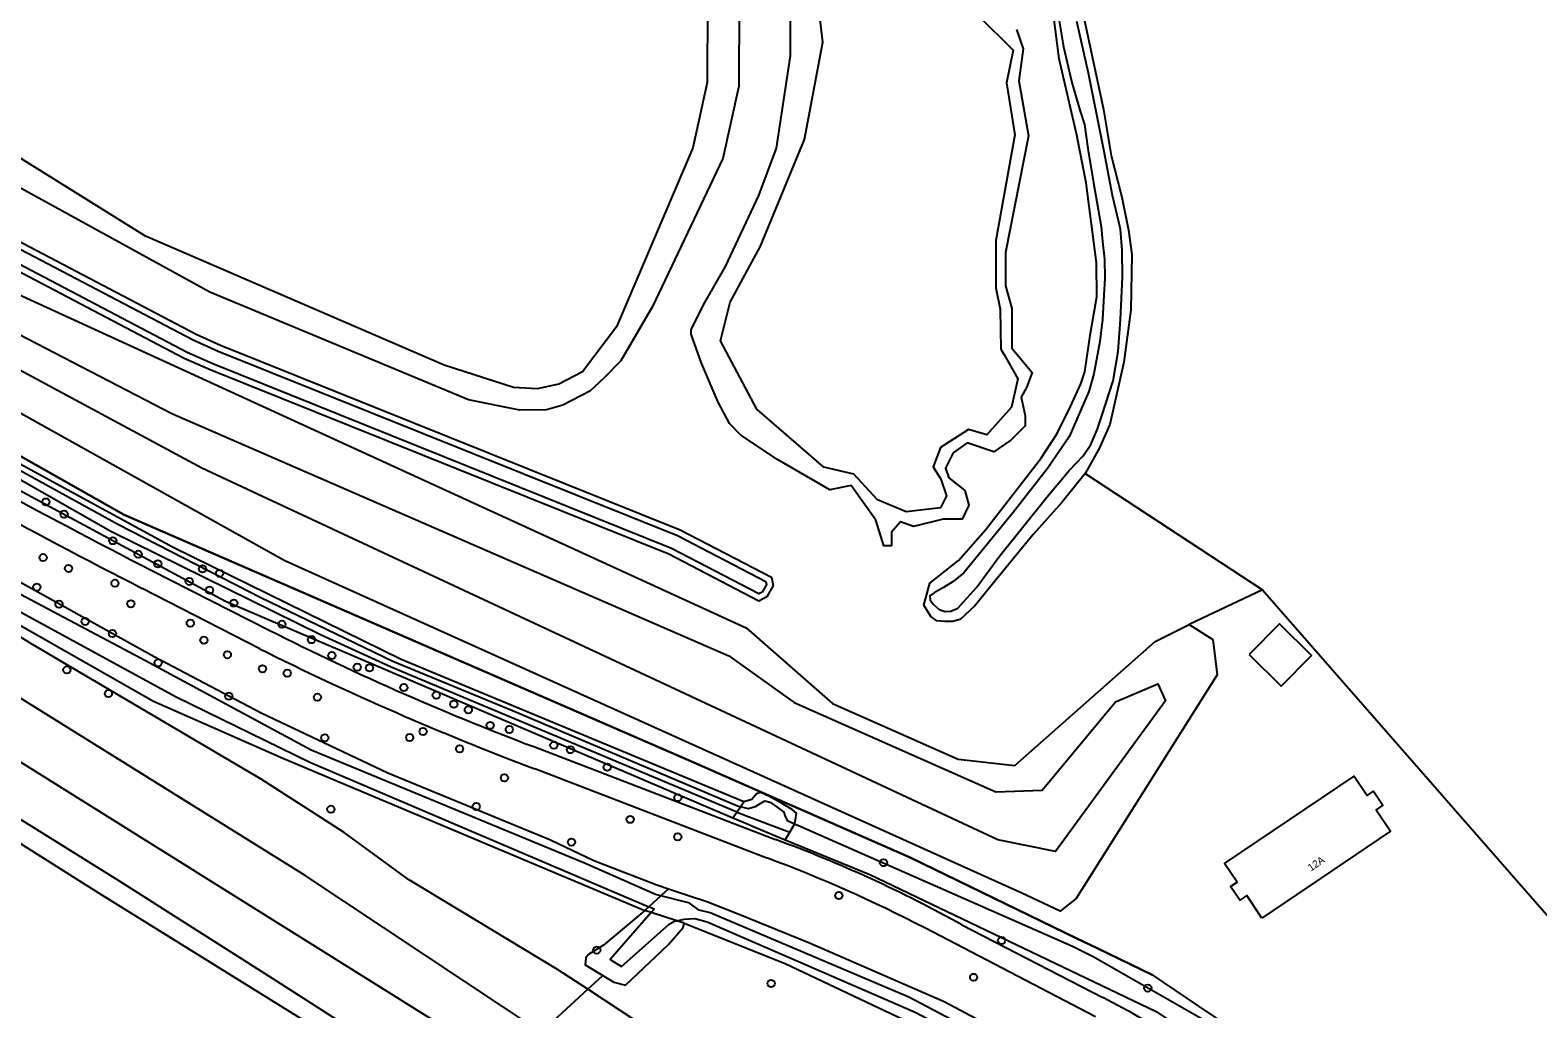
# Model space of a CAD drawing. Extents: x 156502 to 159074, y 384229 to 386094.
# Drawn here: x 158212 to 158415.1, y 384300.6 to 384432.5 of the extents above; entities that cross this region are included whole.
import ezdxf

# ---------------------------------------------------------------- set-up
doc = ezdxf.new("R2010")
doc.units = 0
for name, color, linetype in [('IMGEO_Berm_groen', 7, 'Continuous'), ('IMGEO_Boom', 7, 'Continuous'), ('IMGEO_Duiker', 7, 'Continuous'), ('IMGEO_Fietspad_gesloten', 7, 'Continuous'), ('IMGEO_Gemengd_bos', 7, 'Continuous'), ('IMGEO_Greppel_droge_sloot', 7, 'Continuous'), ('IMGEO_Groenvoorziening', 7, 'Continuous'), ('IMGEO_Hek', 7, 'Continuous'), ('IMGEO_Loofbos', 7, 'Continuous'), ('IMGEO_Meer_plas_ven_vijver', 7, 'Continuous'), ('IMGEO_Oever', 7, 'Continuous'), ('IMGEO_Pand', 7, 'Continuous'), ('IMGEO_Pand_nummerreeks', 7, 'Continuous'), ('IMGEO_Rijbaan_regionaal_gesloten', 7, 'Continuous'), ('IMGEO_Voetpad_onverhard', 7, 'Continuous'), ('IMGEO_Waterloop', 7, 'Continuous')]:
    doc.layers.add(name, color=color, linetype=linetype)

msp = doc.modelspace()

# ---------------------------------------------------------------- linework, layer by layer
at = {"layer": 'IMGEO_Berm_groen'}
msp.add_lwpolyline([(158346.28, 384249.3), (158343.72, 384251.05), (158345.32, 384253.35), (158328.42, 384263.54), (158287.52, 384292.57), (158280.82, 384297.44), (158249.03, 384318.56), (158183.04, 384359.66), (158177.89, 384363.31), (158176.16, 384364.29), (158174.68, 384365.03)], dxfattribs=at)
at = {"layer": 'IMGEO_Boom'}
for centre in [(158214.11, 384368.91), (158216.57, 384367.26), (158223.14, 384363.69), (158213.74, 384361.41), (158226.57, 384361.86), (158217.18, 384359.96), (158229.21, 384360.58), (158235.22, 384359.9), (158237.53, 384359.29), (158212.9, 384357.44), (158223.43, 384357.95), (158233.44, 384358.2), (158236.16, 384357.03), (158215.89, 384355.14), (158225.57, 384355.19), (158239.43, 384355.29), (158219.41, 384352.81), (158223.08, 384351.19), (158233.58, 384352.58), (158245.92, 384352.43), (158235.41, 384350.29), (158249.91, 384350.35), (158229.24, 384347.24), (158238.57, 384348.32), (158252.64, 384348.2), (158216.96, 384346.27), (158243.3, 384346.43), (158246.64, 384345.84), (158256.07, 384346.64), (158257.71, 384346.56), (158222.54, 384343.08), (158238.77, 384342.73), (158262.35, 384343.89), (158266.71, 384342.87), (158250.7, 384342.59), (158269.08, 384341.66), (158271.03, 384340.9), (158273.97, 384338.8), (158251.69, 384337.12), (158263.13, 384337.16), (158264.93, 384337.98), (158276.55, 384338.25), (158269.86, 384335.64), (158282.56, 384336.11), (158284.78, 384335.52), (158289.74, 384333.15), (158275.89, 384331.73), (158299.24, 384329.05), (158252.52, 384327.49), (158272.1, 384327.86), (158292.83, 384326.13), (158284.93, 384323.07), (158299.24, 384323.78), (158326.97, 384320.29), (158320.94, 384315.85), (158288.33, 384308.51), (158342.87, 384309.8), (158339.1, 384304.84), (158311.82, 384304.01), (158362.55, 384303.39)]:
    msp.add_circle(centre, 0.489, dxfattribs=at)
at = {"layer": 'IMGEO_Duiker'}
msp.add_lwpolyline([(158266.52, 384284.33), (158268.57, 384286.21), (158270.47, 384287.95), (158273.25, 384290.5), (158275.97, 384292.99), (158279.21, 384295.96), (158280.82, 384297.44), (158287.13, 384303.22), (158289.15, 384305.08)], dxfattribs=at)
at = {"layer": 'IMGEO_Fietspad_gesloten'}
for points in [[(158228.32, 384359.72), (158244.21, 384351.64)], [(158242.93, 384349.13), (158227.1, 384357.26)], [(158281.01, 384335.49), (158312.39, 384323.41)], [(158311.24, 384320.92), (158279.97, 384332.95)], [(158355.51, 384299.5), (158332.53, 384311.49)], [(158337.53, 384311.89), (158356.49, 384302.12)]]:
    msp.add_lwpolyline(points, dxfattribs=at)
for centre, radius, start, end in [((158650.63, 385184.56), 926.66, 239.75102, 242.8876), ((158661.4, 385204.58), 952.13, 239.79653, 242.86245), ((158408.47, 384675.93), 363.52, 243.1364, 249.4747), ((158420.35, 384704.95), 397.61, 243.4984, 249.3261), ((158251.91, 384158.28), 175.86, 60.8659, 69.8826), ((158246.27, 384145.55), 187.02, 62.5318, 69.6716), ((158276.81, 384149.4), 172.26, 54.3129, 62.446)]:
    msp.add_arc(centre, radius, start, end, dxfattribs=at)
at = {"layer": 'IMGEO_Gemengd_bos'}
for points in [[(157953.37, 384541.5), (158008.57, 384511.11), (158013.49, 384510.03), (158018.06, 384508.82), (158056.86, 384487.45), (158156.93, 384433.61), (158207.36, 384405.7), (158234.35, 384391.53), (158237.66, 384390.06), (158299.55, 384365.16), (158311.85, 384358.78), (158312.11, 384357.63), (158311.23, 384356.11), (158310.18, 384355.56), (158298.04, 384361.86), (158236.25, 384386.72), (158232.77, 384388.27), (158205.64, 384402.51), (158155.19, 384430.42), (158055.13, 384484.27), (158016.71, 384505.43), (158012.64, 384506.5), (158007.28, 384507.68), (157952.13, 384538.04)], [(157951.94, 384537.52), (157962.96, 384531.33), (157976.38, 384524.2), (158000.55, 384511.08), (158022.48, 384499.4), (158033.15, 384493.61), (158043.34, 384488.3), (158064.88, 384476.71), (158089.2, 384463.22), (158100.15, 384457.39), (158109.4, 384452.1), (158158.98, 384424.9), (158174.08, 384416.08), (158199.08, 384402.07), (158308.44, 384351.93), (158320.07, 384341.73), (158337.02, 384334.26), (158344.63, 384333.4), (158363.56, 384350.09), (158368.15, 384352.39)], [(158352.23, 384457.81), (158352.77, 384456.53), (158354.62, 384450.04), (158355.17, 384445.31), (158355.63, 384443.04), (158355.3, 384441.2), (158354.64, 384440.35), (158353.55, 384437.91), (158353.4, 384436.77), (158356.6, 384421.83), (158357.61, 384415.61), (158359.05, 384409.98), (158359.95, 384405.56), (158360.43, 384402.26), (158360.28, 384394.83), (158359.31, 384387.76), (158357.44, 384379.37), (158356.01, 384376.14), (158354.11, 384372.75)], [(158344.88, 384432.61), (158345.78, 384429.97), (158345.2, 384425.68), (158346.48, 384418.26), (158343.37, 384402.54), (158343.37, 384398.05), (158344.24, 384394.98), (158344.24, 384389.66), (158346.99, 384386.36), (158346.23, 384384.35), (158345.51, 384383.05), (158346.05, 384380.53), (158346.05, 384379.18), (158344.1, 384377.23), (158341.82, 384375.66), (158338.23, 384376.9), (158336.36, 384375.53), (158335.29, 384373.47), (158335.78, 384372.17), (158337.91, 384370.47), (158338.46, 384368.46), (158337.57, 384366.59), (158334.98, 384366.59), (158330.98, 384365.59), (158329.26, 384366.22), (158328.05, 384364.84), (158328.05, 384363.01), (158327.47, 384363.01), (158326.98, 384363.01), (158325.91, 384366.45), (158322.59, 384371.12), (158319.71, 384370.55), (158312.68, 384374.62), (158307.72, 384377.9), (158306.2, 384379.5), (158304.68, 384382.36), (158302.46, 384387.6), (158301.06, 384391.53), (158301.06, 384392.1), (158302.71, 384395.5), (158305.66, 384400.64), (158310.17, 384410.2), (158312.56, 384416.6), (158314.43, 384429.03), (158314.43, 384435.84)], [(158354.11, 384372.75), (158350.98, 384368.85), (158347.14, 384364.54), (158342, 384358.29), (158339.26, 384354.91), (158337.3, 384353.05), (158336.26, 384352.79), (158335.24, 384352.8), (158334.13, 384352.9), (158333.32, 384353.47), (158332.74, 384354.4), (158332.4, 384354.98), (158333.19, 384357.95), (158337.06, 384361.04), (158340.68, 384365.16), (158348.14, 384374.77), (158350.33, 384378.16), (158352.15, 384381.78), (158353.54, 384384.82), (158354.08, 384386.45), (158354.83, 384391.68), (158355.68, 384396.57), (158355.63, 384401.15), (158354.27, 384411.91), (158352.98, 384418.34), (158350.62, 384428.64), (158349.64, 384436.36)], [(158354.11, 384372.75), (158378.03, 384357.05)]]:
    msp.add_lwpolyline(points, dxfattribs=at)
at = {"layer": 'IMGEO_Greppel_droge_sloot'}
for points in [[(158377.03, 384275.93), (158353.16, 384290.12), (158330.36, 384302.16), (158303.61, 384313.51), (158302.11, 384313.91), (158300.84, 384314.82), (158300.52, 384314.9), (158296.94, 384315.82)], [(158295.66, 384313.59), (158296.05, 384314.04), (158295.34, 384314.34)], [(158299.13, 384312.46), (158300.1, 384312.67), (158301.56, 384312.76), (158303.21, 384312.33), (158331.22, 384300.12), (158355.82, 384287.1), (158375.31, 384274.49)]]:
    msp.add_lwpolyline(points, dxfattribs=at)
at = {"layer": 'IMGEO_Groenvoorziening'}
for points in [[(158197.11, 384398.46), (158231.1, 384380.85), (158306.12, 384348.19), (158314.92, 384341.9), (158342.07, 384329.83), (158348.35, 384330.08), (158358.23, 384341.96), (158363.93, 384344.41), (158364.94, 384342.09), (158350.11, 384321.79), (158342.36, 384323.38), (158235.12, 384373.47), (158195.19, 384394.95)], [(158308.14, 384328.47), (158262, 384347.66), (158231.26, 384362.77), (158189.91, 384385.3)], [(158204.7, 384373.66), (158238.34, 384355.56), (158306.65, 384326.34)], [(158207.32, 384359.94), (158228.72, 384348.1), (158243.14, 384340.48), (158260.2, 384332.38), (158282.12, 384323.39), (158287.93, 384320.57), (158296.41, 384317.29), (158297.98, 384316.77)], [(158314.98, 384325.5), (158315.09, 384326.08), (158315.24, 384326.95), (158314.64, 384327.47), (158313.2, 384328.32), (158311.52, 384329.27), (158310.45, 384329.73), (158309.86, 384329.55), (158309.24, 384328.81), (158308.14, 384328.47)], [(158306.65, 384326.34), (158308.19, 384325.69), (158309.85, 384324.97), (158312.63, 384323.83), (158313.7, 384323.39)], [(158297.98, 384316.77), (158300.7, 384315.88), (158303.18, 384315.07), (158307.15, 384313.5), (158316.97, 384309.48), (158335.15, 384301.59), (158355.07, 384290.99), (158377.95, 384276.54)]]:
    msp.add_lwpolyline(points, dxfattribs=at)
at = {"layer": 'IMGEO_Hek'}
for points in [[(158310.78, 384329.66), (158301.4, 384333.78), (158224.68, 384367.19), (158139.02, 384415.66), (158112.87, 384430.01), (158110.98, 384431.04)], [(158316.87, 384327), (158310.78, 384329.66)], [(158353, 384310.09), (158330.57, 384320.99), (158316.87, 384327)], [(158355.76, 384308.75), (158353, 384310.09)], [(158363.15, 384305.15), (158355.76, 384308.75)], [(158363.15, 384305.15), (158369.4, 384300.97), (158412.28, 384272.08)]]:
    msp.add_lwpolyline(points, dxfattribs=at)
at = {"layer": 'IMGEO_Loofbos'}
for points in [[(157851.49, 384572.1), (157878.29, 384557.34), (158010.38, 384485.78), (158110.98, 384431.04), (158112.87, 384430.01), (158139.02, 384415.66), (158224.68, 384367.19), (158301.4, 384333.78), (158310.78, 384329.66), (158316.87, 384327), (158330.57, 384320.99), (158353, 384310.09), (158355.76, 384308.75), (158363.15, 384305.15), (158369.4, 384300.97), (158412.28, 384272.08), (158417.33, 384275.58)], [(158368.15, 384352.39), (158371.31, 384350.38), (158371.89, 384345.63), (158352.93, 384315.46), (158350.77, 384313.74), (158345.6, 384316.18), (158246.32, 384360.99), (158192.91, 384390.78), (158165.42, 384405.98), (158136.2, 384422.51), (158113.08, 384435.19), (158097.98, 384443.37), (158091.05, 384446.2), (158088.48, 384447.88), (158085.73, 384449.52), (158083.02, 384450.87), (158079.99, 384452.18), (158077.76, 384453.65), (158076.12, 384454.61), (158072.77, 384456.36), (158067.7, 384458.86), (158064.52, 384460.31)], [(158178, 384370.56), (158180.99, 384368.99), (158195.22, 384361.06), (158228.61, 384342.07), (158246.03, 384334.38), (158294.82, 384313.86)], [(158352.23, 384247.52), (158353.88, 384250), (158355.62, 384253.65), (158354.19, 384256.9), (158353.1, 384258.42), (158345.14, 384265.32), (158322.22, 384281.6), (158315.61, 384286.04), (158309.27, 384289.96), (158295.85, 384297.48), (158287.13, 384303.22), (158283.03, 384305.91), (158262.97, 384318.04), (158254.32, 384324.37), (158243.11, 384331.54), (158212.08, 384349.84), (158195.68, 384360.09), (158180.28, 384367.68), (158177.38, 384369.25)], [(158378.03, 384357.05), (158368.15, 384352.39)], [(158378.03, 384357.05), (158427.25, 384300.73)], [(158294.82, 384313.86), (158289.24, 384309.17), (158287.24, 384307.9), (158286.88, 384307.48), (158286.75, 384306.52), (158290.62, 384304.19), (158292.2, 384303.76), (158297.94, 384309.21), (158299.97, 384311.54), (158300.11, 384312.14)], [(158300.11, 384312.14), (158313.7, 384306.68), (158333.84, 384297.16), (158355.21, 384286.26), (158374.01, 384274.56), (158374.5, 384273.3)]]:
    msp.add_lwpolyline(points, dxfattribs=at)
at = {"layer": 'IMGEO_Meer_plas_ven_vijver'}
for points in [[(158338.42, 384378.7), (158334.62, 384376.26), (158333.64, 384373.63), (158334.7, 384371.97), (158335.43, 384369.76), (158334.62, 384368.11), (158329.99, 384367.6), (158326.13, 384369.21), (158322.98, 384372.65), (158318.91, 384373.58), (158309.9, 384381.4), (158304.98, 384390.65), (158306.3, 384395.84), (158310.37, 384403.39), (158316.32, 384417.75), (158318.78, 384430.91), (158316.4, 384451.29)], [(158339.71, 384434.48), (158344.43, 384429.8), (158343.54, 384425.39), (158344.64, 384418.42), (158342.09, 384404.16), (158342.09, 384402.71), (158342.07, 384397.77), (158342.67, 384394.88), (158342.75, 384389.49), (158343.3, 384388.6), (158345.04, 384385.49), (158344.19, 384381.67), (158340.88, 384377.94), (158338.42, 384378.7)]]:
    msp.add_lwpolyline(points, dxfattribs=at)
at = {"layer": 'IMGEO_Oever'}
for points in [[(158306.65, 384326.34), (158307.2, 384327.12)], [(158307.7, 384327.83), (158308.14, 384328.47)], [(158297.98, 384316.77), (158296.94, 384315.82)], [(158295.34, 384314.34), (158294.82, 384313.86)], [(158295.66, 384313.59), (158294.82, 384313.86)], [(158300.11, 384312.14), (158299.13, 384312.46)]]:
    msp.add_lwpolyline(points, dxfattribs=at)
at = {"layer": 'IMGEO_Pand'}
for points in [[(158376.22, 384348.33), (158380.52, 384344.08), (158384.61, 384348.23), (158380.31, 384352.47), (158376.22, 384348.33)], [(158377.94, 384312.81), (158375.89, 384315.85), (158374.97, 384315.23), (158373.71, 384317.09), (158374.58, 384317.68), (158372.9, 384320.16), (158390.34, 384331.97), (158392.12, 384329.34), (158392.98, 384329.92), (158394.24, 384328.05), (158393.31, 384327.42), (158395.27, 384324.54), (158377.94, 384312.81)]]:
    msp.add_lwpolyline(points, dxfattribs=at)
at = {"layer": 'IMGEO_Rijbaan_regionaal_gesloten'}
for points in [[(158170.69, 384358.72), (158174.26, 384356.66), (158275.97, 384292.99), (158284.45, 384287.13), (158311.53, 384269.23)], [(158339.03, 384242.38), (158328.11, 384249.71), (158296.39, 384270.78), (158280.19, 384281.34), (158270.47, 384287.95), (158269.43, 384288.61), (158257.05, 384296.71), (158245.13, 384304.38), (158224.06, 384317.8), (158202.87, 384330.98), (158199.29, 384333.21), (158177.56, 384346.37), (158170.64, 384350.05), (158166.68, 384352.31)], [(158337.1, 384240.61), (158295.57, 384268.24), (158276.77, 384280.53), (158268.57, 384286.21), (158264.64, 384288.77), (158248.39, 384299.32), (158221.27, 384316.18), (158198.77, 384330.39), (158186.08, 384338.01), (158173.44, 384345.68), (158169.55, 384348.06), (158165.38, 384350.48)]]:
    msp.add_lwpolyline(points, dxfattribs=at)
at = {"layer": 'IMGEO_Voetpad_onverhard'}
for points in [[(158176.27, 384647.19), (158227.88, 384630.66), (158271.55, 384617.44), (158291.92, 384611.42), (158290.79, 384598.64), (158290.98, 384585.92), (158293.04, 384561.96), (158295.49, 384539.36), (158298.34, 384501.83), (158299.02, 384489.12), (158301.49, 384469.15), (158303.07, 384448.16), (158303.26, 384436.06), (158303.2, 384425.43), (158301.25, 384416.63), (158290.99, 384392.5), (158286.43, 384386.45), (158283.2, 384384.77), (158280.29, 384384.16), (158277.1, 384384.33), (158267.78, 384387.36), (158227.54, 384404.72), (158198.62, 384422.74)], [(158297.29, 384562.37), (158299.75, 384539.75), (158302.6, 384502.11), (158303.28, 384489.5), (158305.74, 384469.57), (158307.35, 384448.35), (158307.53, 384436.08), (158307.47, 384424.95), (158305.32, 384415.23), (158295.83, 384395.27), (158291.59, 384387.95), (158289.28, 384385.61), (158287.39, 384383.84), (158283.77, 384381.96), (158281.58, 384381.34), (158277.99, 384381.3), (158271.06, 384382.69), (158236.21, 384397.18), (158153.71, 384442.57)]]:
    msp.add_lwpolyline(points, dxfattribs=at)
at = {"layer": 'IMGEO_Waterloop'}
for points in [[(158296.94, 384315.82), (158296.26, 384315.99), (158286.67, 384320.24), (158249.85, 384335.44), (158227.52, 384347.5), (158177.75, 384373.91), (158161.53, 384381.9), (158140, 384393.28), (158131.89, 384398.12), (158109.68, 384409.92), (158089.43, 384420.71), (157993.04, 384472.77), (157976.65, 384482.02), (157975.84, 384480.58), (157999.53, 384467.46), (158139.45, 384391.92), (158167.64, 384376.84), (158179.07, 384371.32), (158231.68, 384342.66), (158249.68, 384333.83), (158295.34, 384314.34)], [(158350.61, 384433.77), (158351.22, 384430.26), (158352.34, 384425.45), (158353.39, 384421.74), (158354.02, 384419.77), (158354.47, 384416.56), (158355.28, 384411.66), (158356.29, 384406.05), (158356.46, 384404.01), (158356.71, 384401.63), (158356.76, 384399.02), (158356.66, 384396.78), (158356.47, 384393.52), (158356.1, 384390.54), (158355.29, 384386.17), (158354.6, 384383.78), (158351.96, 384377.67), (158349.06, 384373.42), (158344.42, 384367.49), (158337.8, 384359.36), (158336.32, 384358.19), (158335.03, 384357.39), (158333.78, 384356.68), (158333.22, 384356.27), (158333.24, 384355.7), (158333.66, 384355.12), (158334.47, 384354.43), (158335.26, 384354.16), (158336.04, 384354.18), (158336.95, 384354.58), (158339.5, 384357.4), (158342.57, 384361.61), (158348.96, 384369.54), (158351.96, 384373.17), (158353.84, 384375.14), (158354.89, 384376.65), (158355.72, 384378.62), (158356.38, 384380.54), (158357.88, 384385.23), (158358.56, 384389.19), (158358.89, 384393.52), (158359.17, 384399.2), (158359.11, 384402.83), (158358.9, 384405.68), (158357.79, 384410.2), (158356.7, 384416.17), (158354.55, 384426.72), (158353, 384433.67)], [(158206.95, 384404.94), (158233.97, 384390.75), (158237.32, 384389.26), (158299.19, 384364.37), (158311.09, 384358.2), (158311.19, 384357.77), (158310.61, 384356.76), (158310.18, 384356.54), (158298.4, 384362.65), (158236.59, 384387.52), (158233.14, 384389.05), (158206.05, 384403.28)], [(158177.61, 384391.33), (158223.9, 384365.86), (158243.09, 384356.05), (158260.84, 384347.43), (158276.98, 384340.8), (158307.3, 384327.94), (158307.7, 384327.83)], [(158307.2, 384327.12), (158307.11, 384327.16), (158260.63, 384346.66), (158251.11, 384350.99), (158222.88, 384364.92), (158204.53, 384375.37)], [(158307.2, 384327.12), (158307.7, 384327.83)], [(158307.2, 384327.12), (158309.22, 384326.35), (158311.81, 384325.34), (158314.32, 384324.41)], [(158314.98, 384325.5), (158314.31, 384325.79), (158314.07, 384325.9), (158313.71, 384326.63), (158313.56, 384327.11), (158312.48, 384327.9), (158311.83, 384328.36), (158310.96, 384328.58), (158310.39, 384328.26), (158309.69, 384327.83), (158309.66, 384327.83), (158308.76, 384327.54), (158307.7, 384327.83)], [(158313.7, 384323.39), (158325.1, 384318.71), (158363.68, 384300.21), (158383.48, 384286.99), (158384.41, 384287.07), (158384.79, 384287.42), (158384.93, 384289.41), (158370.62, 384298.81), (158355.18, 384307.6), (158352.43, 384308.98), (158315.51, 384325.27), (158314.98, 384325.5)], [(158314.32, 384324.41), (158314.98, 384325.5)], [(158313.7, 384323.39), (158314.32, 384324.41)], [(158296.94, 384315.82), (158295.34, 384314.34)], [(158295.66, 384313.59), (158290.15, 384307.25), (158291.68, 384306.31), (158298.09, 384312), (158298.73, 384312.37), (158299.13, 384312.46)], [(158299.13, 384312.46), (158295.66, 384313.59)]]:
    msp.add_lwpolyline(points, dxfattribs=at)

# ---------------------------------------------------------------- texts
at = {"layer": 'IMGEO_Pand_nummerreeks'}
msp.add_text('12A', height=1, rotation=34.0853, dxfattribs=at).set_placement((158384.53, 384319.08))

doc.saveas('drawing.dxf')
